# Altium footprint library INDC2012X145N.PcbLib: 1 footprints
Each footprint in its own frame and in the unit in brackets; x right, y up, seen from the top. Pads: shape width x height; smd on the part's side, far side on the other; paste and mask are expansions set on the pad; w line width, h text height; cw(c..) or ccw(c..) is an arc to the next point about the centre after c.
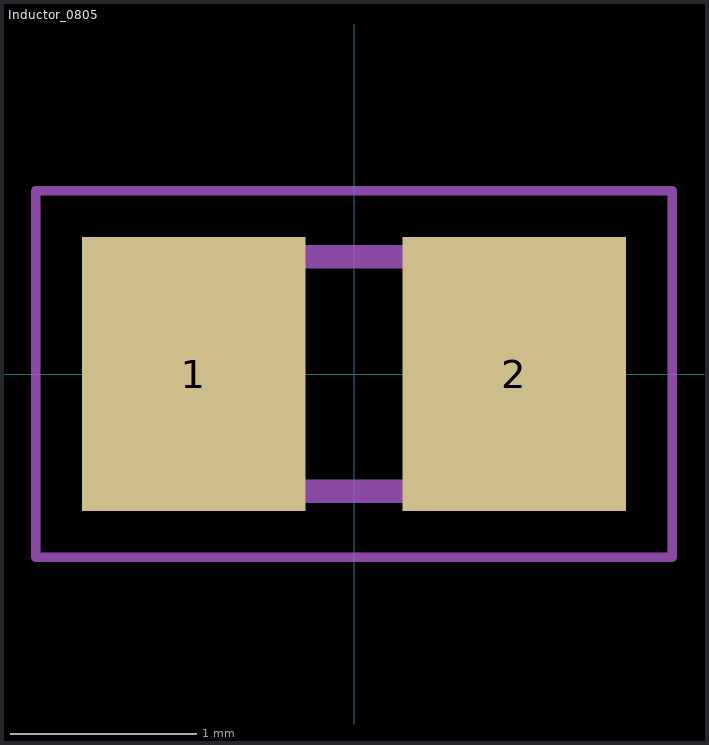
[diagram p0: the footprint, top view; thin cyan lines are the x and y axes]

## Inductor_0805 [mm] "Inductor_0805 MLZ2012M1R5HT000"
pads (2):
  rect 1.2x1.47 smd: 1(-0.86,0) 2(0.86,0)
Mechanical 13:
  lines w0.127: -1,-0.63 -1,0.63 1,0.63 1,-0.63 -1,-0.63
Mechanical 15:
  lines w0.05: -1.708,-0.983 -1.708,0.983 1.708,0.983 1.708,-0.983 -1.708,-0.983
